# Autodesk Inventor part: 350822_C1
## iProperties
Created: 2006-07
Part Number: 350822_C1
Document SubType Name: Modeling
Designer: I.Baliuc
Material: 2.0060
Description: Stromband
Density: 8.94 g/cm^3
Author: T.Messerschmitt
Revision Number: 350822
Comments: Model: C - erstellt für Strombahn DC/Schalter
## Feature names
1. Trennen1
2. Bezeichnung2 [Tagging]
